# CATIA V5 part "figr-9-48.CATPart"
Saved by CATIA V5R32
Part number: Part1
Bounding box of the stored display mesh (mm): x -53.419 to 50, y -50 to 50, z -57.709 to 133.109
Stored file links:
  D:\PROJECTS\Project 2022\CATIA V5 6R 2022\Resources\Part Files\c09_catia_v5_6r2022_prt\c09_catia_v5_6r2022_prt\figr-9-48.CATPart
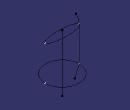
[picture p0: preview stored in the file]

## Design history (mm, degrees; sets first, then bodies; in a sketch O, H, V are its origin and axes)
Body1 (main body)
  Plane1: type Offset, RefPlane xy-plane, Offset 103
  Sketch1 on Plane1, origin (0, 0, 103), H (1, 0, 0), V (0, 1, 0)
    ellipse A1 centre (0, 0) semi-axes 50, 13.2069 rotation 0
    point P1 (50, 0)
    "Radius" A1 = 50
    coincidence: P1 H, A1 P1
  Extremum1: Reference Sketch1, Direction (1, 2, 3)
  Sketch2 on xy-plane, origin (0, 0, 0), H (1, 0, 0), V (0, 1, 0)
    circle A1 centre (0, 0) radius 50
    radius A1 = 50
  Extremum2: Reference Sketch2, Direction (1, 2, 3)
  Sketch3 on zx-plane, origin (0, 0, 0), H (-1, 0, 0), V (0, 0, 1)
    spline S1 through (37.7591, -31.0289) (41.8235, -21.251) (50, 0) (49.8084, 85.7657) (50, 103) (41.6255, 133.1089)
    reference projected line E1 (-50, 103) -> (50, 103) from Sketch1.A1
    point P1 (50, 0)
    point P2 (50, 103)
    distance V P1 = 50
    distance P2 V = 50
    coincidence: P1 H, P2 E1
  Sketch4 on zx-plane, origin (0, 0, 0), H (-1, 0, 0), V (0, 0, 1)
    line L1 (0, 111.062) -> (0, -57.7094)
    point P1 (0, 111.062)
    coincidence: P1 V
    vertical: L1 V
  Loft1: solid, Sections (Sketch1; Sketch2), Spine Sketch4, Guides Sketch3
